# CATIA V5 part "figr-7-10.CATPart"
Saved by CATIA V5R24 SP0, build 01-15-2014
Part number: Part1
Bounding box of the stored display mesh (mm): x -50 to 50, y -62.5 to 62.5, z 0 to 100
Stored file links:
  D:\KAVITA\CATIA V5-6R2014 Project_ Kavita\CATIA V5-6R2014_partfiles\Partfiles\c07_catia_v5-6r2014_prt\figr-7-10.CATPart
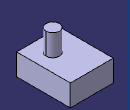
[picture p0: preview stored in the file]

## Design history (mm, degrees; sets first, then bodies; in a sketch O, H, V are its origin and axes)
Body1 (main body)
  Sketch1 on xy-plane, origin (0, 0, 0), H (1, 0, 0), V (0, 1, 0)
    line L1 (-50, 62.5) -> (50, 62.5)
    line L2 (50, 62.5) -> (50, -62.5)
    line L3 (50, -62.5) -> (-50, -62.5)
    line L4 (-50, -62.5) -> (-50, 62.5)
    axis line L5 (50, -62.5) -> (-50, 62.5)
    length L3 = 100
    length L2 = 125
    horizontal: L1 H, L3 H
    vertical: L2 V, L4 V
    midpoint: O L5
  Pad1: profile Sketch1, direction (0, 0, 1), length 50
  Sketch2 on face of Pad1, origin (0, 0, 50), H (1, 0, 0), V (0, 1, 0)
    circle A1 centre (8.7691, -19.7725) radius 15.5717
  Pad2: profile Sketch2, direction (0, 0, 1), length 50
  Sketch3 on face of Pad1, origin (0, 62.5, 112.5), H (1, 0, 0), V (0, 0, -1)
    circle A1 centre (2.1924, 87.7667) radius 15.5717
